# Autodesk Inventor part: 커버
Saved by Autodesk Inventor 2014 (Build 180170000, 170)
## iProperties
Created: 2025-10
Part Number: 커버
Material: 일반
Document SubType Name: Modeling
Designer: dg
Density: 1 g/cm^3
Appearance: 기본값
Author: dg
Author: jhkim
Creation Date: 2025-10-01
Sending System: Autodesk Inventor 2026
Preprocessor: ST-DEVELOPER v20.1
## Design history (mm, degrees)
node "커버1"
node "솔리드1"
node "기준1"
